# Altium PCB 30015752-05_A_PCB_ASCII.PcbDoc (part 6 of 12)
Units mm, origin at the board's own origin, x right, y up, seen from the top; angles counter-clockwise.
Board outline 100.05 x 72 mm, 10 copper layers (Top, GND_2, Signal_3, Signal_4, PWR_5, GND_6, Signal_7, Signal_8, GND_9, Bottom), stack 1.493 mm thick; 577 components, 546 nets, 2389 pads, 1412 vias.
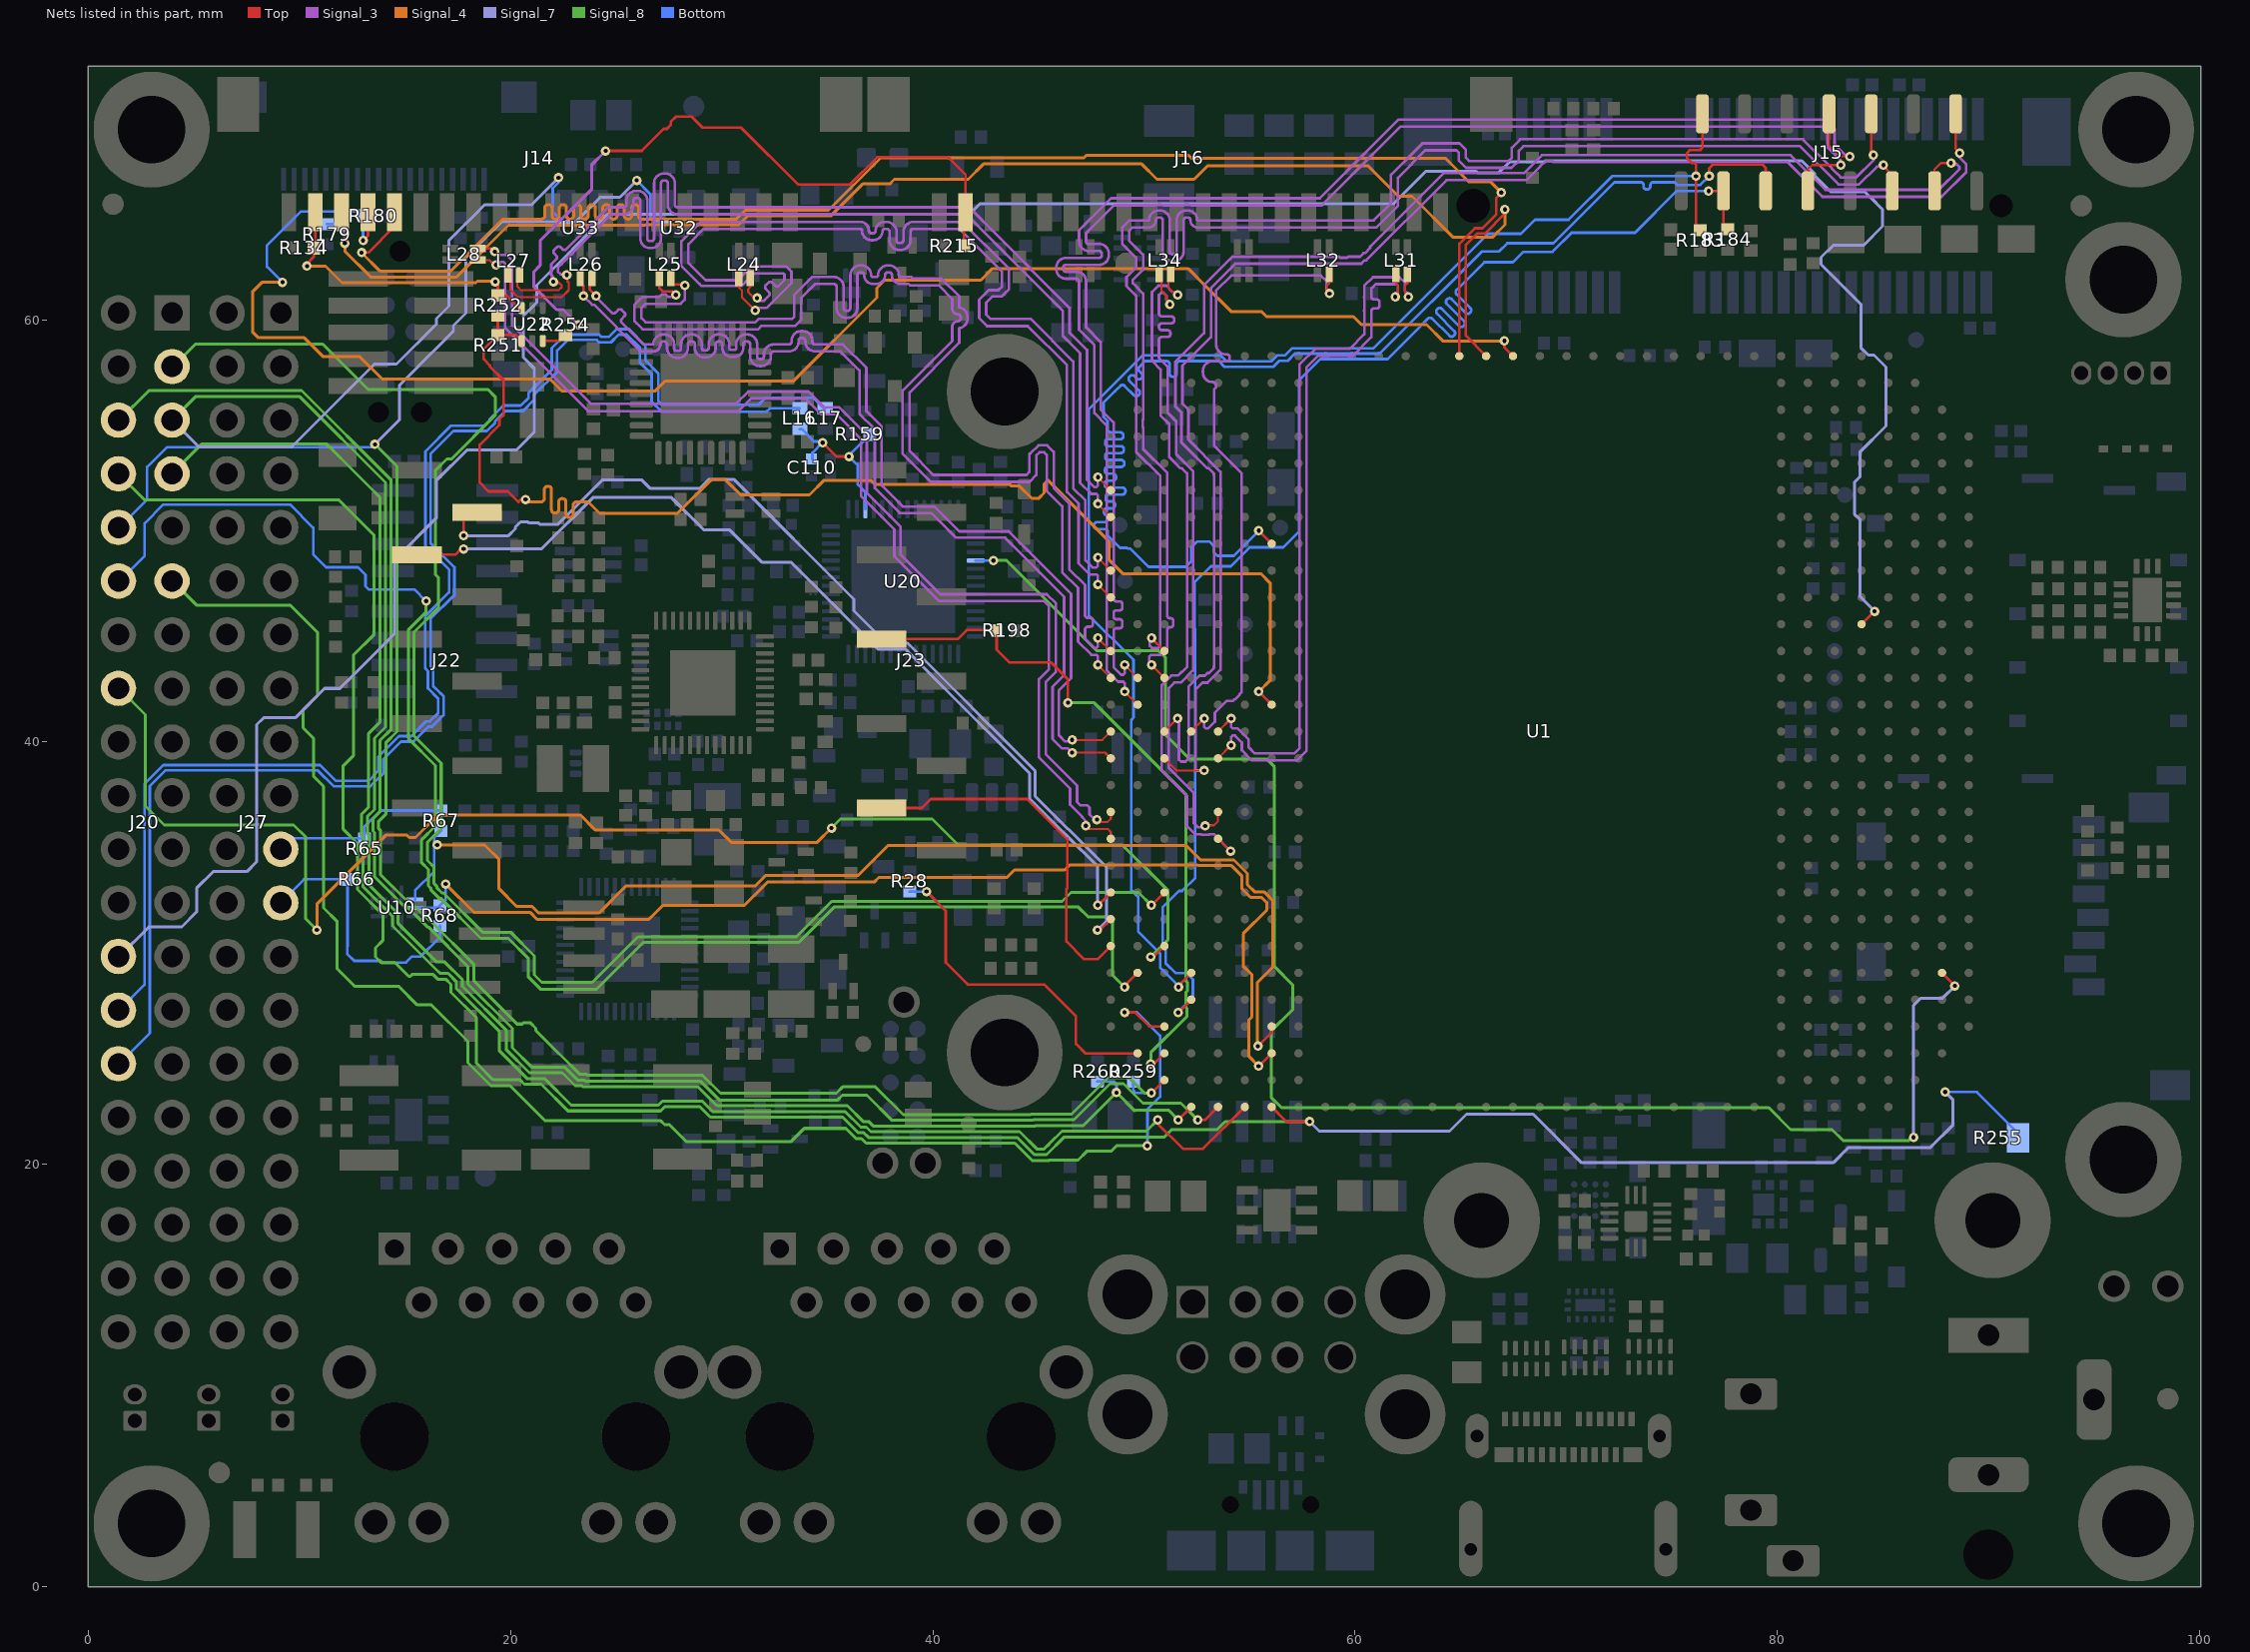
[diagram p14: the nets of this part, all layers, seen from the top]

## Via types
v1: diameter 0.45, hole 0.2, Top to Bottom, tented both sides, 1412 vias

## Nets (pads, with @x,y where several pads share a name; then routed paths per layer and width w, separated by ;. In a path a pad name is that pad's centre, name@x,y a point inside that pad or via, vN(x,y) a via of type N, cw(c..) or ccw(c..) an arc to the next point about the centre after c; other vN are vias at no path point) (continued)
LTE_SYNC: J20.26 U1.E11 | length 136.6
  Top w0.127: U1.E11@83.99,45.58 84.6,46.19 v1(84.61,46.19)
  Signal_7 w0.142: J20.26@1.46,29.84 2.87,31.25 4.423,31.25 5.125,31.952 5.125,33.075 5.915,33.865 7.51,33.865 7.975,34.33 7.975,40.825 8.3,41.15 9.802,41.15 11.192,42.54 11.919,42.54 14.512,45.133 14.512,48.633 16.479,50.6 16.479,52.379 17.925,53.825 20.275,53.825 21.112,54.662 21.112,57.706 20.602,58.215 20.602,60.179 21.238,60.815 21.238,61.643 24.59,64.995 41.732,64.995 42.231,65.494 61.819,65.494 63.346,67.021 65.738,67.021 65.79,66.969 66.81,66.969 67.312,67.471 68.953,67.471 69.005,67.523 81.16,67.523 81.773,66.91 81.773,66.818 82.521,66.071 84.128,66.071 84.412,65.787 84.423,65.787 84.987,65.223 84.987,64.427 84.085,63.525 82.637,63.525 82.075,62.963 82.075,62.621 83.96,60.737 83.96,58.675 84.31,58.325 84.58,58.325 85.148,57.757 85.148,54.973 83.908,53.733 83.908,52.553 83.648,52.294 83.648,50.8 83.923,50.525 83.923,46.877 v1(84.61,46.19)
M40_UART_RX: J27.23 R66.1 R68.1 | length 12.8
  Bottom w0.127: J27.23@9.1,32.38 10.22,33.5 12.22,33.5 12.245,33.475 R66.1@12.245,33.5 12.275,33.47 12.275,30.338 12.259,30.322 12.259,29.978 12.597,29.641 13.849,29.641 13.929,29.561 15.048,29.561 15.329,29.842 15.742,29.842 16.65,30.75 R68.1@16.65,31.295
M40_UART_RX_1V8: R68.2 U1.AG27 U10.9 | length 53.6
  Top w0.127: v1(55.43,24.65) 55.44,24.65 U1.AG27@56.05,25.26
  Signal_4 w0.142: v1(16.925,33.275) 18.26,31.94 20.915,31.94 21.256,31.6 26.55,31.6 27.206,32.256 31.056,32.256 32.167,33.367 37.217,33.367 37.437,33.587 43.512,33.587 43.869,33.944 46.25,33.944 46.488,34.183 52.538,34.183 52.573,34.148 54.151,34.148 54.631,33.668 54.631,33.069 55.057,32.643 55.575,32.643 55.823,32.395 55.823,32.045 54.7,30.922 54.7,29.396 55.106,28.99 55.106,26.979 54.977,26.85 54.977,25.103 v1(55.43,24.65)
  Bottom w0.127: U10.9@15.475,32.15 16.545,32.15 R68.2@16.65,32.255 16.925,32.53 v1(16.925,33.275)
M40_UART_TX: J27.21 R65.1 R67.1 | length 8.7
  Bottom w0.127: J27.21@9.1,34.92 9.63,35.45 13.055,35.45 R65.1@13.075,35.43 13.075,36 13.83,36.755 R67.1@16.7,36.755
M40_UART_TX_1V8: R67.2 U1.AG26 U10.8 | length 56.6
  Top w0.127: v1(55.4,25.6) 56.05,26.25 U1.AG26@56.05,26.53
  Signal_4 w0.142: v1(16.526,35.127) 18.773,35.127 19.45,34.45 19.45,33.05 20.29,32.21 21.027,32.21 21.336,31.9 24.179,31.9 25.463,33.183 31.583,33.183 32.075,33.675 36.45,33.675 37.875,35.1 52.002,35.1 52.685,34.417 54.262,34.417 54.9,33.779 54.9,33.25 55.238,32.912 55.687,32.912 56.092,32.507 56.092,29.328 55.375,28.611 55.375,25.625 v1(55.4,25.6)
  Bottom w0.127: U10.8@15.475,32.55 15.475,32.962 16.385,33.873 16.385,35.48 R67.2@16.7,35.795
MCA_CLKOUT32K: J20.3 U1.AL21 | length 82
  Top w0.127: v1(50.35,32.27) 50.36,32.27 U1.AL21@50.97,32.88
  Signal_8 w0.142: J20.3@4,57.78 5.07,58.85 11.1,58.85 13.246,56.704 18.921,56.704 19.271,56.354 19.271,55.473 17.209,53.41 16.986,53.41 16.43,52.854 16.43,47.947 16.573,47.804 16.573,46.35 15.421,45.198 15.421,40.29 16.712,39 16.712,35.911 16.057,35.256 16.057,34.397 16.378,34.076 16.378,33.297 16.502,33.173 16.502,33.1 16.75,32.852 16.823,32.852 18.7,30.975 20.025,30.975 21.122,29.878 21.122,28.972 21.477,28.617 23.873,28.617 26.031,30.775 33.531,30.775 35.208,32.452 46.127,32.452 46.55,32.875 49.745,32.875 v1(50.35,32.27)
MCA_IO5: J20.10 R259.1 U1.AL28 U32.4 | length 104
  Top w0.127: v1(50.35,23.38) 50.36,23.38 U1.AL28@50.97,23.99
  Signal_8 w0.142: v1(13.575,54.1) 14.613,53.062 14.613,40.489 14.088,39.963 14.088,36.586 13.752,36.25 13.752,35.9 13.827,35.825 13.827,33.735 15.016,32.546 15.141,32.546 16.181,31.506 16.228,31.506 18.251,29.483 18.251,28.701 20.306,26.646 20.548,26.646 20.6,26.698 20.95,26.698 21.198,26.45 21.198,26.341 22.323,25.215 22.331,25.215 23.285,24.262 23.598,24.262 23.645,24.215 29.097,24.215 29.942,23.369 35.428,23.369 35.729,23.67 37.28,23.67 38.598,22.352 38.699,22.352 38.701,22.354 40.601,22.354 40.603,22.352 44.621,22.352 44.651,22.382 46.576,22.382 48.294,24.1 49.3,24.1 50.02,23.38 v1(50.35,23.38)
  Signal_7 w0.142: v1(13.575,54.1) 14.725,55.25 14.725,56.883 17.292,59.45 17.292,59.721 17.883,60.312 17.883,62.958 19.562,64.637 23.088,64.637 24.255,65.803 25.178,65.803 v1(25.975,66.6)
  Bottom w0.127: J20.10@1.46,50.16 2.788,51.488 2.788,53.03 3.728,53.97 13.445,53.97 v1(13.575,54.1) ; v1(25.975,66.6) 26.619,65.955 26.619,64.881 26.9,64.6 U32.4@27.19,64.6 ; R259.1@49.5,23.92 49.5,23.5 49.62,23.38 v1(50.35,23.38)
MCA_IO6: J20.5 R260.1 U1.AK29 U33.4 | length 107.8
  Top w0.127: v1(51.62,22.11) 51.63,22.11 U1.AK29@52.24,22.72
  Signal_8 w0.142: J20.5@3.965,55.245 5.095,56.375 9.994,56.375 14.075,52.294 14.075,40.712 13.549,40.186 13.549,36.809 13.213,36.473 13.213,35.677 13.288,35.602 13.288,33.248 14.675,31.862 14.675,31.404 16.498,29.581 16.881,29.581 17.712,28.75 17.712,28.43 19.81,26.333 19.81,25.413 20.886,24.337 22.448,24.337 23.062,23.723 23.375,23.723 23.422,23.676 28.874,23.676 29.77,22.78 35.951,22.78 36.7,22.031 36.96,22.031 37.176,21.815 38.346,21.815 38.348,21.813 38.922,21.813 38.924,21.815 40.378,21.815 40.38,21.813 44.844,21.813 44.874,21.843 47.143,21.843 v1(48.7,23.4) 49.563,22.537 49.602,22.575 51.155,22.575 v1(51.62,22.11)
  Signal_7 w0.142: J20.5@3.965,55.245 5.235,53.975 9.625,53.975 13.55,57.9 14.6,57.9 16.485,59.785 16.485,60.056 17.075,60.646 17.075,63.75 18.769,65.444 20.994,65.444 v1(22.275,66.725)
  Bottom w0.127: v1(22.275,66.725) 22.275,66.512 21.994,66.232 21.994,65.121 U33.4@22.515,64.6 ; R260.1@47.8,23.92 48.58,23.92 48.7,23.8 v1(48.7,23.4)
MCA_IO7: J20.6 U1.AJ29 | length 82
  Top w0.127: v1(52.55,22.1) 52.89,22.1 U1.AJ29@53.51,22.72
  Signal_8 w0.142: J20.6@1.46,55.24 2.87,56.65 10.1,56.65 14.344,52.406 14.344,40.6 13.818,40.075 13.818,36.698 13.483,36.362 13.483,35.788 13.558,35.713 13.558,33.623 14.904,32.277 15.023,32.277 15.95,31.35 ; 15.951,31.35 16.064,31.236 16.117,31.236 17.982,29.371 17.982,28.541 20.079,26.444 20.079,25.525 20.998,24.606 22.56,24.606 23.173,23.992 23.487,23.992 23.534,23.945 28.985,23.945 29.882,23.049 35.489,23.049 35.715,23.275 36.875,23.275 38.066,22.084 38.458,22.084 38.459,22.083 38.811,22.083 38.812,22.084 40.49,22.084 40.491,22.083 44.733,22.083 44.763,22.113 46.688,22.113 48.398,23.823 49.031,23.823 49.954,22.9 51.75,22.9 v1(52.55,22.1)
MCA_IO8: J20.7 U1.AH29 | length 80.4
  Top w0.127: v1(50.65,22.1) 50.65,21.937 51.853,20.735 52.794,20.735 U1.AH29@54.78,22.72
  Signal_8 w0.142: J20.7@3.965,52.705 5.385,54.125 11.273,54.125 12.723,52.675 13.271,52.127 13.806,51.593 13.806,40.932 13.28,40.407 13.28,36.921 12.944,36.585 12.944,35.565 13.019,35.49 13.019,33.137 14.406,31.75 14.406,31.292 16.435,29.263 16.443,29.263 16.662,29.044 17.038,29.044 17.443,28.638 17.443,28.318 19.475,26.286 19.475,25.367 20.775,24.067 21.608,24.067 22.875,22.8 26.996,22.8 27.19,22.993 29.082,22.993 29.575,22.5 35.85,22.5 36.588,21.762 36.848,21.762 37.064,21.546 38.234,21.546 38.236,21.544 39.034,21.544 39.036,21.546 40.266,21.546 40.268,21.544 44.107,21.544 44.925,20.727 45.275,20.727 45.523,20.975 45.523,20.979 46.118,21.574 50.124,21.574 v1(50.65,22.1)
MCA_IO9: J20.8 R255.2 U1.AG29 | length 126.3
  Top w0.127: U1.AG29@56.05,22.72 56.745,22.025 v1(57.85,22.025)
  Signal_8 w0.142: J20.8@1.425,52.705 2.655,51.475 11.85,51.475 13.537,49.788 13.537,45.1 12.55,44.113 12.55,39.35 12.075,38.875 12.075,35.875 12.75,35.2 12.75,33.025 13.95,31.825 13.95,30.6 13.6,30.25 13.6,29.825 13.875,29.55 14.525,29.55 15.175,28.9 15.245,28.9 15.339,28.994 16.331,28.994 16.55,28.775 16.926,28.775 17.174,28.527 17.174,28.151 18.375,26.95 18.375,24.8 19.175,24 20.444,24 20.646,23.798 21.45,23.798 22.718,22.531 27.108,22.531 27.301,22.724 28.97,22.724 29.463,22.231 29.994,22.231 30,22.225 35.744,22.225 36.477,21.492 36.737,21.492 36.954,21.275 37.113,21.275 37.115,21.277 38.123,21.277 38.125,21.275 39.145,21.275 39.147,21.277 40.155,21.277 40.157,21.275 43.996,21.275 44.813,20.458 45.387,20.458 46.228,21.299 50.974,21.299 51.325,21.65 53.475,21.65 53.85,22.025 v1(57.85,22.025)
  Signal_7 w0.142: v1(57.85,22.025) 58.3,21.575 64.475,21.575 65.277,22.377 68.433,22.377 70.733,20.077 82.652,20.077 83.375,20.8 87.25,20.8 88.325,21.875 88.325,23.05 v1(87.95,23.425)
  Bottom w0.127: v1(87.95,23.425) 89.45,23.425 91.4,21.475 R255.2@91.4,21.25
MCA_IO14: J20.11 U1.AL26 | length 78
  Top w0.127: v1(49.08,27.2) 49.582,27.2 50.252,26.53 U1.AL26@50.97,26.53
  Signal_8 w0.142: J20.11@4,47.62 5.147,46.473 9.577,46.473 10.85,45.2 10.85,42.2 10.175,41.525 10.175,40.675 10.673,40.177 10.673,38.372 11.141,37.903 11.141,32.144 11.787,31.498 11.787,29.264 12.61,28.44 13.955,28.44 13.963,28.433 14.537,28.433 14.545,28.44 14.69,28.44 15.581,27.55 16.256,27.55 17.978,25.828 17.978,24.809 19.061,23.725 19.975,23.725 21.638,22.061 27.118,22.061 27.301,21.878 27.522,21.878 28.315,21.085 33.29,21.085 33.909,21.703 35.885,21.703 36.365,21.223 36.625,21.223 36.843,21.006 37.225,21.006 37.227,21.007 38.011,21.007 38.013,21.006 39.257,21.006 39.259,21.007 40.043,21.007 40.045,21.006 43.884,21.006 44.702,20.188 45.498,20.188 45.512,20.202 46.875,20.202 47.291,20.618 48.445,20.618 48.703,20.876 v1(50.152,20.876)
  Bottom w0.127: v1(49.08,27.2) 49.658,27.2 50.766,26.092 50.766,23.208 50.166,22.608 50.166,20.889 v1(50.152,20.876)
MCA_IO17: J20.16 U1.AL23 | length 69
  Top w0.127: v1(50.325,29.825) 50.455,29.825 U1.AL23@50.97,30.34
  Signal_8 w0.142: J20.16@1.46,42.54 2.7,41.3 2.7,36.975 3.6,36.075 9.725,36.075 10.3,35.5 10.3,31.625 v1(10.825,31.1) ; v1(35.2,35.925) 35.625,36.35 39.975,36.35 41.2,35.125 48.975,35.125 51.144,32.956 51.144,31.192 51.129,31.177 51.129,30.826 51.144,30.811 51.144,30.644 v1(50.325,29.825)
  Signal_4 w0.142: v1(10.825,31.1) 10.825,32.325 14.092,35.592 15.087,35.592 15.204,35.475 15.488,35.475 16.563,36.55 23.3,36.55 24.025,35.825 29.875,35.825 30.448,35.252 34.527,35.252 v1(35.2,35.925)
MCA_UART2_CTS: J23.9 U1.AN23 | length 17.3
  Top w0.127: J23.9@37.567,36.875 39.475,36.875 39.9,37.3 44.475,37.3 46.368,35.407 46.368,33.08 46.325,33.037 46.325,30.55 47.15,29.725 47.815,29.725 U1.AN23@48.43,30.34
MCA_UART2_RTS: J23.5 R198.2 U1.AL27 | length 33.4
  Top w0.127: J23.5@37.567,44.875 41.175,44.875 41.6,45.3 43.02,45.3 R198.2@43.02,45.275 43.02,44.38 43.625,43.775 45.591,43.775 46.4,42.966 v1(46.4,41.86) ; v1(50.325,24.75) 50.46,24.75 U1.AL27@50.97,25.26
  Signal_8 w0.142: v1(46.4,41.86) 47.643,41.86 51.998,37.505 51.998,28.68 52.057,28.621 52.057,28.217 51.998,28.158 51.998,27.41 52.043,27.365 52.043,27.015 50.325,25.297 v1(50.325,24.75)
MCA_UART2_RX: J22.2 U1.AN22 | length 46.6
  Top w0.127: v1(17.775,49.775) 17.775,50.725 17.625,50.875 J22.2@18.417,50.875 ; v1(47.8,31.1) 47.92,31.1 U1.AN22@48.43,31.61
  Signal_7 w0.142: v1(17.775,49.775) 19.9,49.775 20.227,50.102 20.227,50.175 20.475,50.423 20.825,50.423 20.877,50.371 21.329,50.371 21.402,50.298 22.237,50.298 24.364,52.426 26.199,52.426 26.623,52.002 28.962,52.002 29.388,52.428 30.592,52.428 36.26,46.76 36.26,46.217 37.8,44.677 38.809,44.677 44.85,38.637 44.85,37.432 46.4,35.883 46.412,35.883 48.233,34.061 48.233,31.533 v1(47.8,31.1)
MCA_UART2_TX: J22.3 U1.AN21 | length 44
  Top w0.127: J22.3@15.567,48.875 17.375,48.875 17.65,49.15 v1(17.775,49.15) ; v1(47.81,32.27) 47.82,32.27 U1.AN21@48.43,32.88
  Signal_7 w0.142: v1(17.775,49.15) 21.469,49.15 23.899,51.58 25.5,51.58 ; 25.501,51.579 25.852,51.579 27.62,51.58 29.162,50.038 30.381,50.038 31.9,48.519 33.281,48.519 37.392,44.408 38.698,44.408 40.613,42.492 40.613,42.485 44.581,38.518 44.581,37.321 46.288,35.613 46.301,35.613 47.81,34.104 v1(47.81,32.27)
MCA_VIN_DET: R28.2 U1.AM27 | length 16.2
  Top w0.127: v1(39.7,32.92) 40.616,32.004 40.616,29.559 41.654,28.521 45.264,28.521 46.779,27.005 46.779,25.708 47.237,25.25 49.69,25.25 U1.AM27@49.7,25.26
  Bottom w0.127: R28.2@38.9,32.92 v1(39.7,32.92)
MCA_VREF_OUT: J20.12 U1.AM24 | length 75.8
  Top w0.127: v1(49.08,28.4) 49.08,28.45 U1.AM24@49.7,29.07
  Signal_8 w0.142: v1(16,46.675) 16,46.157 15.152,45.309 15.152,40.179 16.442,38.888 16.442,36.022 15.788,35.368 15.788,34.286 16.108,33.965 16.108,33.186 16.233,33.062 16.233,32.988 16.638,32.583 16.712,32.583 18.589,30.706 19.894,30.706 20.85,29.75 20.85,28.863 21.413,28.3 24.075,28.3 26.281,30.506 33.642,30.506 35.32,32.183 46.892,32.183 47.35,31.725 48.275,31.725 48.5,31.5 48.5,28.98 v1(49.08,28.4)
  Bottom w0.127: J20.12@1.46,47.62 2.664,48.824 2.664,50.366 3.548,51.25 9.552,51.25 10.649,50.153 10.649,48.891 11.265,48.275 12.775,48.275 13.125,47.925 13.125,47.375 13.275,47.225 15.45,47.225 v1(16,46.675)
MCLK_OUT0: U1.B24 U20.5 | length 77.6
  Top w0.127: U1.B24@87.8,29.07 88.41,28.46 v1(88.41,28.45)
  Signal_8 w0.142: v1(42.875,48.6) 43.5,48.6 47.78,44.32 50.7,44.32 51.025,43.995 51.025,40.325 52.15,39.2 55.805,39.2 56.18,38.825 56.18,29.36 57.04,28.5 57.04,27.325 56.025,26.31 56.025,23.175 56.52,22.68 79.6,22.68 80.632,21.648 82.598,21.648 83.113,21.133 86.224,21.133 86.367,21.275 v1(86.45,21.275)
  Signal_7 w0.142: v1(86.45,21.275) 86.45,27.525 86.8,27.875 87.835,27.875 v1(88.41,28.45)
  Bottom w0.127: U20.5@42.03,48.6 v1(42.875,48.6)
MIC_BIAS: C110.2 L16.2 R159.1 U20.45 | length 8.1
  Top w0.127: v1(34.78,54.18) 35.435,53.525 v1(36.025,53.525)
  Bottom w0.127: L16.2@33.7,54.82 33.79,54.82 34.373,54.237 34.688,54.237 34.745,54.18 v1(34.78,54.18) 34.3,53.7 C110.2@34.3,53.4 ; U20.45@36.8,51.03 36.8,51.836 36.441,52.195 36.441,53.11 v1(36.025,53.525) 36.025,53.57 37.005,54.55 R159.1@37.005,54.575
MIC_N: J20.28 L17.1 | length 66.3
  Bottom w0.127: J20.28@1.46,27.3 2.655,28.495 2.655,38.017 3.548,38.909 10.975,38.909 11.725,38.159 13.259,38.159 13.725,38.625 13.725,39.29 14.712,40.278 15.3,40.278 16.003,40.98 16.177,40.98 16.57,41.373 16.57,42.059 16.083,42.545 16.083,43.36 15.954,43.489 15.954,45.954 17.084,47.084 17.084,48.176 15.966,49.294 15.966,53.765 17.185,54.985 18.772,54.985 19.016,55.228 19.016,55.303 19.647,55.935 20.485,55.935 20.85,56.3 20.85,56.53 21.95,57.63 21.95,58.65 22.6,59.3 24.187,59.3 24.303,59.184 24.647,59.184 25.017,59.554 25.605,59.554 26.379,58.78 26.379,58.081 27,57.46 27,56.155 27.18,55.975 31.75,55.975 32.075,56.3 34.34,56.3 34.835,55.805 L17.1@34.9,55.805
MIC_P: J20.30 L16.1 | length 67.1
  Bottom w0.127: J20.30@1.46,24.76 2.909,26.209 2.909,37.912 3.653,38.655 10.87,38.655 11.62,37.905 13.365,37.905 13.979,38.52 13.979,39.185 14.817,40.024 15.405,40.024 16.108,40.726 16.283,40.726 16.824,41.267 16.824,42.173 16.687,42.309 16.678,42.309 16.434,42.553 16.434,42.559 16.385,42.608 16.379,42.608 16.337,42.65 16.337,43.466 16.208,43.595 16.208,45.833 17.338,46.963 17.338,48.281 16.22,49.399 16.22,53.66 17.29,54.731 18.877,54.731 19.27,55.123 19.27,55.198 19.752,55.681 20.59,55.681 21.104,56.195 21.104,56.425 22.204,57.525 22.204,58.545 22.705,59.046 24.082,59.046 24.198,58.93 24.752,58.93 25.122,59.3 25.5,59.3 26.125,58.675 26.125,57.975 26.68,57.42 26.68,56.115 27.145,55.65 32.125,55.65 32.28,55.805 L16.1@33.7,55.805
MIPI0_IRQ_N_5V: J14.19 R134.1 R252.2 U22.6 | length 14.1
  Top w0.127: v1(10.36,62.54) 10.36,62.66 10.68,62.98 R134.1@10.68,63.4 10.75,63.47 J14.19@10.75,65.1 ; v1(19.275,61.8) 19.4,61.675 R252.2@19.4,61.155 19.795,61.155 20.395,60.555 U22.6@20.525,60.555
  Signal_4 w0.142: v1(10.36,62.54) 11.235,62.54 12.021,61.754 18.356,61.754 18.425,61.823 19.252,61.823 v1(19.275,61.8)
MIPI1_IRQ_N_5V: J16.19 R215.1 R254.2 U22.3 | length 36.1
  Top w0.127: U22.3@21.525,58.995 22.325,58.995 R254.2@22.6,59.27 23.08,59.75 v1(23.225,59.75) ; v1(24.5,68) 26.212,68 27.253,69.041 27.403,69.041 27.584,69.222 27.584,69.372 27.828,69.615 28.584,69.615 29.1,69.1 30.925,69.1 33.617,66.407 36.083,66.407 37.375,67.7 40.725,67.7 41.55,66.875 J16.19@41.55,65.1 41.48,65.03 R215.1@41.48,63.5
  Signal_3 w0.142: v1(23.225,59.75) 22.494,60.481 22.179,60.481 21.106,61.554 21.106,62.282 21.398,62.575 21.398,63.742 23.848,66.192 23.848,67.348 v1(24.5,68)
MIPI_CSI0_CLK_N: J15.8 U1.AM14 | length 69.8
  Top w0.102: v1(49.09,42.39) 49.09,42.38 U1.AM14@49.7,41.77 ; J15.8@82.45,69.75 82.45,68.25 82.966,67.734 v1(83.432,67.734)
  Signal_3 w0.124: v1(49.09,42.39) 49.09,42.787 49.017,42.86 48.777,42.86 48.234,43.403 48.234,54.999 47.65,55.583 47.65,58.803 46.928,59.525 46.928,61.819 ccw(c46.798,61.819) 46.798,61.948 46.307,61.948 cw(c46.307,62.408) 45.847,62.408 45.847,62.473 cw(c46.307,62.473) 46.307,62.933 47.879,62.933 ccw(c47.879,63.063) 48.008,63.063 48.008,63.128 ccw(c47.879,63.128) 47.879,63.258 47.387,63.258 cw(c47.387,63.717) 46.928,63.717 46.928,64.236 48.447,65.755 58.33,65.755 62.055,69.48 82.262,69.48 82.709,69.033 82.709,68.312 83.287,67.734 v1(83.432,67.734)
MIPI_CSI0_CLK_P: J15.7 U1.AM13 | length 69.7
  Top w0.102: v1(49.09,43.66) 49.09,43.65 U1.AM13@49.7,43.04 ; J15.7@81.45,66.1 81.45,67.125 81.675,67.35 81.697,67.328 v1(83.004,67.328)
  Signal_3 w0.124: v1(49.09,43.66) 49.09,43.263 49.017,43.19 48.914,43.19 48.564,43.54 48.564,45.125 48.564,45.262 cw(c48.692,45.262) 48.692,45.389 48.847,45.389 ccw(c48.847,45.517) 48.974,45.517 48.974,45.687 ccw(c48.847,45.687) 48.847,45.814 48.692,45.814 cw(c48.692,45.941) 48.564,45.941 48.564,46.111 cw(c48.692,46.111) 48.692,46.238 48.847,46.238 ccw(c48.847,46.366) 48.974,46.366 48.974,46.535 ccw(c48.847,46.535) 48.847,46.663 48.692,46.663 cw(c48.692,46.79) 48.564,46.79 48.564,46.875 48.564,55.136 47.95,55.75 47.95,58.95 47.258,59.642 47.258,61.819 ccw(c46.798,61.819) 46.798,62.278 46.307,62.278 cw(c46.307,62.408) 46.177,62.408 46.177,62.473 cw(c46.307,62.473) 46.307,62.603 47.879,62.603 ccw(c47.879,63.063) 48.338,63.063 48.338,63.128 ccw(c47.879,63.128) 47.879,63.588 47.387,63.588 cw(c47.387,63.717) 47.258,63.717 47.258,64.099 48.584,65.425 50.518,65.425 50.525,65.432 50.566,65.432 50.57,65.436 50.625,65.436 50.633,65.443 50.647,65.443 50.65,65.446 50.81,65.446 50.812,65.443 50.827,65.443 50.834,65.436 50.889,65.436 50.893,65.432 50.935,65.432 50.941,65.425 51.827,65.425 51.834,65.432 51.876,65.432 51.88,65.436 51.935,65.436 51.942,65.443 51.956,65.443 51.959,65.446 52.119,65.446 52.122,65.443 52.136,65.443 52.143,65.436 52.198,65.436 52.202,65.432 52.244,65.432 52.251,65.425 58.425,65.425 62.15,69.15 82.125,69.15 82.379,68.896 82.379,68.175 83.004,67.55 v1(83.004,67.328)
MIPI_CSI0_DATA0_N: J15.14 U1.AL16 | length 69.5
  Top w0.102: U1.AL16@50.97,39.23 51.55,38.65 v1(52.85,38.65) ; J15.14@88.45,69.75 88.45,68.09 v1(88.64,67.9)
  Signal_3 w0.124: v1(52.85,38.65) 52.525,38.65 52.446,38.729 52.446,42.486 52.771,42.811 53.016,42.811 53.63,43.426 53.63,52.799 52.108,54.321 52.108,55.74 51.82,56.028 51.82,57.82 53.176,59.176 53.176,61.499 54.335,62.658 60.297,62.658 60.453,62.814 60.527,62.814 64.326,66.613 68.129,66.613 68.766,67.25 68.766,67.272 69.008,67.514 69.352,67.514 69.404,67.462 80.5,67.462 82.138,65.824 87.78,65.824 88.952,66.996 88.952,67.373 v1@88.612,67.713
MIPI_CSI0_DATA0_P: J15.13 U1.AL15 | length 69.9
  Top w0.102: U1.AL15@50.97,40.5 51.58,41.11 v1(51.59,41.11) ; J15.13@87.45,66.1 87.45,67.125 87.75,67.425 v1(88.225,67.425)
  Signal_3 w0.124: v1(51.59,41.11) 51.66,41.04 51.66,39.165 51.75,39.075 51.975,39.075 52.116,39.216 52.116,42.623 52.635,43.142 52.879,43.142 52.998,43.261 53.072,43.261 53.314,43.503 53.314,43.577 53.325,43.588 53.325,52.637 53.314,52.648 53.314,52.722 53.072,52.964 52.998,52.964 51.778,54.185 51.778,55.603 51.49,55.891 51.49,58.015 52.846,59.371 52.846,61.635 54.198,62.988 59.232,62.988 59.281,62.939 59.624,62.939 59.673,62.988 60.234,62.988 60.41,63.164 60.475,63.164 60.717,63.407 60.717,63.471 64.189,66.943 67.992,66.943 68.841,67.792 80.637,67.792 82.275,66.154 87.643,66.154 88.622,67.133 88.622,67.236 88.495,67.363 88.287,67.363 v1(88.225,67.425)
MIPI_CSI0_DATA1_N: J15.11 U1.AL13 | length 69.7
  Top w0.102: v1(50.36,43.66) 50.36,43.65 U1.AL13@50.97,43.04 ; v1(85.029,67.328) 85.029,67.271 85.45,66.85 J15.11@85.45,66.1
  Signal_3 w0.124: v1(50.36,43.66) 50.25,43.77 50.25,44.05 50.33,44.13 50.822,44.13 51.104,44.412 51.104,45.325 cw(c51.218,45.325) 51.218,45.438 51.261,45.438 ccw(c51.261,45.566) 51.388,45.566 51.388,45.735 ccw(c51.261,45.735) 51.261,45.863 51.232,45.863 cw(c51.232,45.99) 51.104,45.99 51.104,46.075 51.104,52.738 49.958,53.884 49.958,54.906 49.946,54.918 49.946,55.262 49.958,55.274 49.958,61.242 49.475,61.725 49.475,61.892 49.958,62.375 49.958,63.092 49.3,63.75 49.3,64.225 49.45,64.375 50.229,64.375 ccw(c50.229,64.714) 50.567,64.714 cw(c50.697,64.714) 50.697,64.843 50.762,64.843 cw(c50.762,64.714) 50.892,64.714 50.892,63.235 ccw(c51.352,63.235) 51.352,62.775 51.417,62.775 ccw(c51.417,63.235) 51.877,63.235 51.877,64.714 cw(c52.006,64.714) 52.006,64.843 52.072,64.843 cw(c52.072,64.714) 52.201,64.714 ccw(c52.54,64.714) 52.54,64.375 61.017,64.375 62.03,65.388 62.03,66.727 63.328,68.025 64.806,68.025 64.906,67.924 64.906,67.552 65.263,67.195 67.412,67.195 67.755,67.538 67.755,68.011 67.969,68.225 81.072,68.225 82.892,66.406 83.864,66.406 84.713,67.254 84.954,67.254 v1(85.029,67.328)
MIPI_CSI0_DATA1_P: J15.10 U1.AL12 | length 69.6
  Top w0.102: v1(50.36,44.93) 50.36,44.92 U1.AL12@50.97,44.31 ; J15.10@84.45,69.75 84.45,67.858 84.505,67.803 v1(84.554,67.803)
  Signal_3 w0.124: 50.229,64.705 49.313,64.705 48.97,64.362 48.97,63.605 49.628,62.947 49.628,62.478 49.175,62.025 49.175,61.591 49.628,61.138 49.628,53.747 50.774,52.601 50.774,46.1 50.768,46.093 50.768,45.99 50.765,45.99 50.765,45.952 50.771,45.946 50.771,45.909 50.774,45.905 50.774,45.868 50.774,45.443 50.773,45.442 50.773,45.407 50.77,45.404 50.77,45.367 50.766,45.362 50.766,45.325 50.768,45.325 50.768,45.222 50.774,45.215 50.774,44.549 50.685,44.46 50.38,44.46 50.28,44.56 50.28,44.85 v1(50.36,44.93) ; 50.237,64.714 cw(c50.697,64.714) 50.697,65.174 50.762,65.174 cw(c50.762,64.714) 51.222,64.714 51.222,63.235 ccw(c51.352,63.235) 51.352,63.105 51.417,63.105 ccw(c51.417,63.235) 51.547,63.235 51.547,64.714 cw(c52.006,64.714) 52.006,65.174 52.072,65.174 cw(c52.072,64.714) 52.531,64.714 ; 52.54,64.705 60.88,64.705 61.7,65.525 61.7,66.864 63.191,68.355 64.942,68.355 65.236,68.061 65.236,67.689 65.4,67.525 67.275,67.525 67.425,67.675 67.425,68.148 67.833,68.555 81.209,68.555 82.59,67.174 82.59,67.157 82.832,66.914 82.85,66.914 83.028,66.736 83.727,66.736 84.554,67.563 v1(84.554,67.803)
MIPI_CSI0_I2C0_SCL: J15.3 R184.1 U1.AK25 | length 69.4
  Top w0.127: v1(51.62,27.19) 51.63,27.19 U1.AK25@52.24,27.8 ; v1(76.75,66.1) 77.425,66.1 J15.3@77.45,66.075 ; J15.3@77.45,66.1 J15.3@77.45,66.075 ; R184.1@77.5,64.23 77.45,64.28 J15.3@77.45,66.075
  Bottom w0.127: v1(51.62,27.19) 52.32,27.89 52.32,28.76 52.019,29.061 51.499,29.061 51.029,29.531 51.029,30.252 50.883,30.398 50.883,32.171 51.658,32.946 51.805,32.946 52.429,33.57 52.429,45.33 52.4,45.36 52.4,47.557 53.167,48.325 54.114,48.325 55.01,49.221 56.596,49.221 57.34,49.965 57.34,57.126 58.357,58.142 61.537,58.142 63.222,59.828 63.319,59.925 63.447,60.052 cw(c63.551,59.948) 63.655,60.052 64.467,59.24 ccw(c64.571,59.344) 64.675,59.24 64.698,59.263 ccw(c64.594,59.367) 64.698,59.471 63.886,60.283 cw(c63.99,60.387) 63.886,60.491 63.909,60.514 cw(c64.013,60.41) 64.117,60.514 64.929,59.702 ccw(c65.033,59.806) 65.137,59.702 65.16,59.725 ccw(c65.056,59.829) 65.16,59.933 64.348,60.746 cw(c64.452,60.85) 64.348,60.954 64.371,60.977 cw(c64.475,60.873) 64.58,60.977 65.229,60.327 ccw(c65.333,60.431) 65.437,60.327 65.461,60.35 ccw(c65.357,60.454) 65.461,60.558 64.811,61.208 cw(c64.915,61.312) 64.811,61.416 64.822,61.428 66.121,62.726 67.476,62.726 67.967,63.217 69.351,63.217 70.259,64.125 73.263,64.125 75.238,66.1 v1(76.75,66.1)
MIPI_CSI0_I2C0_SDA: J15.2 R183.1 U1.AK24 | length 70.2
  Top w0.127: v1(51.634,28.393) 51.634,28.456 51.63,28.46 U1.AK24@52.24,29.07 ; R183.1@76.35,64.23 76.3,64.28 76.34,64.32 76.15,64.51 v1(76.15,66.8) 76.15,67.35 76.075,67.425 75.95,67.425 75.725,67.65 75.725,67.9 75.863,68.037 76.338,68.037 76.45,68.15 J15.2@76.45,69.75
  Bottom w0.127: v1(51.634,28.393) 51.634,28.446 50.775,29.305 50.775,29.975 49.725,31.025 49.725,32.675 49.4,33 49.4,41.05 49.505,41.156 49.505,43.894 47.385,46.015 47.385,55.747 49.958,58.32 53.63,58.32 53.925,58.025 56.025,58.025 56.309,58.309 56.675,58.309 57.016,58.65 60.875,58.65 66.3,64.075 67.863,64.075 68.528,64.741 70.116,64.741 72.175,66.8 v1(76.15,66.8)
MIPI_CSI0_RESET_N: J15.5 U1.AG8 | length 67.3
  Top w0.127: v1(55.44,50.01) 55.44,50 U1.AG8@56.05,49.39 ; v1(76.775,66.8) 76.775,67.175 76.95,67.35 79.3,67.35 79.45,67.2 J15.5@79.45,66.1
  Bottom w0.127: v1(55.44,50.01) 54.25,48.82 53.48,48.82 53.321,48.98 53.321,49.275 53.095,49.5 52.525,49.5 52.252,49.227 52.252,48.572 51.98,48.3 50.212,48.3 49.357,49.155 49.245,49.155 49.2,49.2 48.875,49.2 48.278,49.797 48.278,49.925 48.278,49.942 ccw(c48.131,49.942) 48.131,50.089 47.786,50.089 cw(c47.786,50.237) 47.638,50.237 47.638,50.269 cw(c47.786,50.269) 47.786,50.416 48.131,50.416 ccw(c48.131,50.564) 48.278,50.564 48.278,50.72 ccw(c48.255,50.72) 48.255,50.743 cw(c48.255,50.891) 48.108,50.891 48.108,50.923 cw(c48.255,50.923) 48.255,51.07 48.278,51.07 48.482,51.07 ccw(c48.482,51.218) 48.629,51.218 48.629,51.25 ccw(c48.482,51.25) 48.482,51.397 48.278,51.397 cw(c48.278,51.484) 48.192,51.484 48.192,51.638 cw(c48.278,51.638) 48.278,51.724 48.976,51.724 ccw(c48.976,51.872) 49.123,51.872 49.123,51.904 ccw(c48.976,51.904) 48.976,52.051 48.278,52.051 cw(c48.278,52.189) 48.141,52.189 48.141,52.241 cw(c48.278,52.241) 48.278,52.378 48.527,52.378 ccw(c48.527,52.526) 48.675,52.526 48.675,52.558 ccw(c48.527,52.558) 48.527,52.705 48.278,52.705 cw(c48.278,52.824) 48.16,52.824 48.16,52.914 cw(c48.278,52.914) 48.278,53.032 48.925,53.032 ccw(c48.925,53.18) 49.072,53.18 49.072,53.212 ccw(c48.925,53.212) 48.925,53.359 48.278,53.359 cw(c48.278,53.458) 48.18,53.458 48.18,53.588 cw(c48.278,53.588) 48.278,53.686 48.9,53.686 ccw(c48.9,53.834) 49.047,53.834 49.047,53.866 ccw(c48.9,53.866) 48.9,54.013 48.278,54.013 cw(c48.278,54.125) 48.167,54.125 48.167,54.229 cw(c48.278,54.229) 48.278,54.34 48.874,54.34 ccw(c48.874,54.488) 49.021,54.488 49.021,54.52 ccw(c48.874,54.52) 48.874,54.667 48.426,54.667 cw(c48.426,54.815) 48.278,54.815 48.278,54.831 48.278,55.197 48.084,55.391 48.084,56.072 48.637,56.625 48.753,56.741 48.88,56.868 cw(c48.984,56.764) 49.088,56.868 49.532,56.424 ccw(c49.636,56.528) 49.74,56.424 49.763,56.447 ccw(c49.659,56.551) 49.763,56.655 49.32,57.099 cw(c49.424,57.203) 49.32,57.307 49.343,57.33 cw(c49.447,57.226) 49.551,57.33 49.66,57.221 ccw(c49.764,57.325) 49.868,57.221 49.891,57.244 ccw(c49.787,57.348) 49.891,57.452 49.782,57.561 cw(c49.886,57.666) 49.782,57.77 49.894,57.881 50.058,58.046 50.725,58.046 50.888,58.046 51.068,58.046 cw(c51.068,57.899) 51.215,57.899 51.215,57.448 ccw(c51.363,57.448) 51.363,57.3 51.395,57.3 ccw(c51.395,57.448) 51.542,57.448 51.542,57.899 cw(c51.69,57.899) 51.69,58.046 51.7,58.046 53.545,58.046 53.82,57.771 56.13,57.771 56.415,58.055 56.805,58.055 57.146,58.396 61.171,58.396 66.009,63.234 66.822,63.234 67.213,63.625 69.4,63.625 72.291,66.516 73.525,66.516 cw(c73.525,66.381) 73.659,66.381 73.659,66.322 ccw(c73.807,66.322) 73.807,66.175 73.839,66.175 ccw(c73.839,66.322) 73.986,66.322 73.986,66.368 cw(c74.134,66.368) 74.134,66.516 74.15,66.516 75.131,66.516 75.262,66.385 76.359,66.385 v1(76.775,66.8)
MIPI_DSI0_CLK_N: L27.1 U1.AN6 | length 49.8
  Top w0.102: L27.1@20.425,62.125 20.315,62.015 20.315,61.572 20.49,61.397 22.276,61.397 22.422,61.543 22.422,61.627 22.302,61.747 22.078,61.747 v1(22.025,61.8) ; v1(47.82,52.55) 47.82,52.54 U1.AN6@48.43,51.93
  Signal_3 w0.124: v1(22.025,61.8) 21.974,61.851 21.974,62.083 21.928,62.129 21.928,62.63 22.099,62.801 22.159,62.861 ccw(c22.069,62.951) 22.159,63.041 22.068,63.132 cw(c22.158,63.222) 22.068,63.312 22.188,63.432 cw(c22.278,63.342) 22.368,63.432 22.459,63.342 ccw(c22.549,63.432) 22.639,63.342 22.747,63.45 24.623,65.326 25.358,65.326 ccw(c25.358,65.455) 25.487,65.455 25.487,65.646 cw(c25.947,65.646) 25.947,66.106 26.012,66.106 cw(c26.012,65.646) 26.472,65.646 26.472,63.855 ccw(c26.602,63.855) 26.602,63.726 26.667,63.726 ccw(c26.667,63.855) 26.797,63.855 26.797,66.466 cw(c27.256,66.466) 27.256,66.926 27.322,66.926 cw(c27.322,66.466) 27.781,66.466 27.781,65.455 ccw(c27.911,65.455) 27.911,65.326 41.716,65.326 42.712,64.33 46.48,60.562 46.48,59.4 47.305,58.575 47.305,52.419 47.644,52.08 47.747,52.08 47.82,52.153 v1(47.82,52.55)
MIPI_DSI0_CLK_P: L27.4 U1.AN7 | length 49.9
  Top w0.102: L27.4@19.875,62.125 19.985,62.015 19.985,61.435 20.353,61.067 22.413,61.067 22.752,61.406 22.752,61.764 22.698,61.818 22.698,62.052 22.66,62.09 v1(22.66,62.12) ; v1(47.82,51.28) 47.82,51.27 U1.AN7@48.43,50.66
  Signal_3 w0.124: v1(22.66,62.12) 22.63,62.12 22.596,62.154 22.37,62.154 22.244,62.28 22.244,62.48 22.315,62.55 22.324,62.55 22.397,62.623 22.398,62.622 22.426,62.649 22.426,62.656 22.452,62.683 22.452,62.688 22.478,62.714 22.786,63.022 22.812,63.048 22.817,63.048 22.844,63.075 22.851,63.075 22.879,63.102 22.877,63.104 22.95,63.177 22.95,63.186 24.76,64.995 25.358,64.995 ccw(c25.358,65.455) 25.817,65.455 25.817,65.646 cw(c25.947,65.646) 25.947,65.776 26.012,65.776 cw(c26.012,65.646) 26.142,65.646 26.142,63.855 ccw(c26.602,63.855) 26.602,63.395 26.667,63.395 ccw(c26.667,63.855) 27.127,63.855 27.127,66.466 cw(c27.256,66.466) 27.256,66.595 27.322,66.595 cw(c27.322,66.466) 27.451,66.466 27.451,65.455 ccw(c27.911,65.455) 27.911,64.995 41.58,64.995 46.15,60.425 46.15,59.25 46.975,58.425 46.975,52.282 47.507,51.75 47.747,51.75 47.82,51.677 v1(47.82,51.28)
MIPI_DSI0_DATA0_N: L24.1 U1.AN9 | length 49.3
  Top w0.102: L24.1@31.35,61.975 31.35,61.549 31.256,61.455 31.258,61.454 31.258,61.307 31.54,61.025 31.543,61.028 v1(31.677,61.028) ; v1(47.82,48.74) 47.82,48.73 U1.AN9@48.43,48.12
  Signal_3 w0.124: v1(31.677,61.028) 31.677,60.973 31.652,60.948 31.698,60.902 32,60.902 32.174,61.076 32.234,61.136 ccw(c32.144,61.226) 32.234,61.316 32.093,61.457 cw(c32.183,61.547) 32.093,61.637 32.213,61.757 cw(c32.303,61.667) 32.393,61.757 32.534,61.616 ccw(c32.624,61.706) 32.714,61.616 32.975,61.877 32.975,62.15 32.925,62.2 31.542,62.2 31.033,61.692 30.937,61.595 29.049,61.595 28.952,61.692 28.095,62.549 28.095,63.72 28.908,64.533 29.005,64.63 36.571,64.63 cw(c36.571,64.23) 36.972,64.23 ccw(c37.102,64.23) 37.102,64.1 37.167,64.1 ccw(c37.167,64.23) 37.297,64.23 cw(c37.697,64.23) 37.697,64.63 37.822,64.63 cw(c37.822,64.171) 38.281,64.171 38.281,63.76 ccw(c38.411,63.76) 38.411,63.63 38.476,63.63 ccw(c38.476,63.76) 38.606,63.76 38.606,64.171 cw(c39.066,64.171) 39.066,64.63 41.388,64.63 43.605,62.413 43.605,61.439 43.266,61.1 42.817,61.1 42.525,60.808 42.525,60.25 42.725,60.05 44.625,60.05 46.65,58.025 46.65,52.017 47.23,51.437 47.23,48.606 47.566,48.27 47.747,48.27 47.82,48.343 v1(47.82,48.74)
MIPI_DSI0_DATA0_P: L24.4 U1.AN10 | length 49.3
  Top w0.102: L24.4@30.8,61.975 30.8,61.549 30.954,61.395 30.954,61.069 31.575,60.448 v1(31.588,60.448) ; v1(47.82,47.47) 47.82,47.46 U1.AN10@48.43,46.85
  Signal_3 w0.124: v1(31.588,60.448) 31.588,60.461 31.698,60.571 32.137,60.571 33.208,61.643 33.305,61.74 33.305,62.287 33.208,62.383 33.062,62.53 31.405,62.53 31.275,62.4 30.75,61.875 29.235,61.875 28.425,62.685 28.425,63.583 29.142,64.3 36.571,64.3 cw(c36.571,64.23) 36.642,64.23 ccw(c37.102,64.23) 37.102,63.77 37.167,63.77 ccw(c37.167,64.23) 37.627,64.23 cw(c37.697,64.23) 37.697,64.3 37.822,64.3 cw(c37.822,64.171) 37.951,64.171 37.951,63.76 ccw(c38.411,63.76) 38.411,63.3 38.476,63.3 ccw(c38.476,63.76) 38.936,63.76 38.936,64.171 cw(c39.066,64.171) 39.066,64.3 41.251,64.3 43.275,62.276 43.275,61.576 43.099,61.4 42.65,61.4 42.195,60.945 42.195,60.075 42.57,59.7 44.495,59.7 46.35,57.845 46.35,51.85 46.9,51.3 46.9,48.469 47.43,47.94 47.747,47.94 47.82,47.867 v1(47.82,47.47)
MIPI_DSI0_DATA1_N: L25.1 U1.AN12 | length 54.8
  Top w0.102: v1(47.82,44.93) 47.82,44.92 U1.AN12@48.43,44.31
  Top w0.124: L25.1@27.6,61.975 27.6,61.75 27.675,61.675 28.2,61.675 v1(28.25,61.625)
  Signal_3 w0.124: v1(28.25,61.625) 28.25,60.95 28.06,60.76 26.385,60.76 26.2,60.575 26.2,60.075 26.392,59.883 31.596,59.883 31.747,60.034 31.76,60.034 31.771,60.044 33.344,60.044 33.43,60.13 33.43,61.172 34.283,62.025 35.312,62.025 cw(c35.312,61.565) 35.772,61.565 35.772,60.554 ccw(c35.902,60.554) 35.902,60.425 35.967,60.425 ccw(c35.967,60.554) 36.097,60.554 36.097,62.114 cw(c36.556,62.114) 36.556,62.574 36.622,62.574 cw(c36.622,62.114) 37.081,62.114 ccw(c37.17,62.114) 37.17,62.025 37.317,62.025 ccw(c37.317,62.114) 37.406,62.114 cw(c37.866,62.114) 37.866,62.574 37.931,62.574 cw(c37.931,62.114) 38.391,62.114 ccw(c38.48,62.114) 38.48,62.025 38.991,62.025 39.058,61.958 40.409,61.958 41.249,61.118 41.249,60.584 cw(c41.189,60.128) 41.649,60.128 41.649,60.063 cw(c41.189,60.063) 41.249,59.607 41.249,58.909 38.9,56.561 38.9,53.775 40.023,52.652 44.438,52.652 44.57,52.784 44.57,53.661 44.617,53.661 45.012,54.055 45.412,54.055 45.73,53.737 45.73,52.041 46.463,51.308 46.463,48.187 47.212,47.438 47.212,46.1 47.212,46.015 ccw(c47.339,46.015) 47.339,45.888 47.449,45.888 cw(c47.449,45.76) 47.577,45.76 47.577,45.591 cw(c47.449,45.591) 47.449,45.463 47.339,45.463 ccw(c47.339,45.336) 47.212,45.336 47.212,45.25 47.212,44.892 47.644,44.46 47.747,44.46 47.82,44.533 v1(47.82,44.93)
MIPI_DSI0_DATA1_P: L25.4 U1.AN13 | length 54.8
  Top w0.102: v1(47.82,43.66) 47.82,43.65 U1.AN13@48.43,43.04
  Top w0.124: L25.4@27.05,61.975 27.05,61.5 27.201,61.349 27.651,61.349 v1(27.825,61.175)
  Signal_3 w0.124: v1(27.825,61.175) 27.74,61.09 27.46,61.09 27.35,61.2 27.16,61.2 27.05,61.09 26.248,61.09 26.089,60.931 25.967,60.808 25.87,60.712 25.87,59.938 25.967,59.842 26.255,59.553 31.732,59.553 31.894,59.714 33.481,59.714 33.76,59.993 33.76,61.035 34.42,61.695 35.312,61.695 cw(c35.312,61.565) 35.442,61.565 35.442,60.554 ccw(c35.902,60.554) 35.902,60.095 35.967,60.095 ccw(c35.967,60.554) 36.427,60.554 36.427,62.114 cw(c36.556,62.114) 36.556,62.243 36.622,62.243 cw(c36.622,62.114) 36.751,62.114 ccw(c37.17,62.114) 37.17,61.695 37.317,61.695 ccw(c37.317,62.114) 37.736,62.114 cw(c37.866,62.114) 37.866,62.243 37.931,62.243 cw(c37.931,62.114) 38.061,62.114 ccw(c38.48,62.114) 38.48,61.695 38.854,61.695 38.921,61.628 40.272,61.628 40.918,60.982 40.918,60.528 ccw(c41.189,60.528) 41.189,60.258 cw(c41.189,60.128) 41.318,60.128 41.318,60.063 cw(c41.189,60.063) 41.189,59.933 ccw(c41.189,59.663) 40.918,59.663 40.918,58.999 38.574,56.654 38.574,53.651 39.903,52.322 44.575,52.322 44.9,52.647 44.9,53.575 45.05,53.725 45.275,53.725 45.4,53.6 45.4,51.904 46.133,51.171 46.133,48.05 46.882,47.301 46.882,44.755 47.507,44.13 47.747,44.13 47.82,44.057 v1(47.82,43.66)
MIPI_DSI0_DATA2_N: L26.1 U1.AN15 | length 48
  Top w0.102: v1(46.6,40.1) 48.03,40.1 U1.AN15@48.43,40.5
  Top w0.124: L26.1@23.85,61.975 23.75,61.875 23.75,61.425 v1(24.05,61.125)
  Signal_3 w0.124: v1(24.05,61.125) 24.05,61.078 24.728,60.4 24.788,60.34 ccw(c24.878,60.43) 24.968,60.34 25.091,60.463 cw(c25.181,60.373) 25.271,60.463 25.391,60.343 cw(c25.301,60.253) 25.391,60.163 25.268,60.04 ccw(c25.358,59.95) 25.268,59.86 25.326,59.801 26.298,58.83 26.751,58.83 ; 26.762,58.841 cw(c27.222,58.841) 27.222,59.301 27.287,59.301 cw(c27.287,58.841) 27.747,58.841 27.747,58.653 ccw(c27.877,58.653) 27.877,58.523 27.942,58.523 ccw(c27.942,58.653) 28.072,58.653 28.072,58.841 cw(c28.531,58.841) 28.531,59.301 28.597,59.301 cw(c28.597,58.841) 29.056,58.841 29.056,58.665 ccw(c29.167,58.665) 29.167,58.554 29.27,58.554 ccw(c29.27,58.665) 29.381,58.665 29.381,58.841 cw(c29.841,58.841) 29.841,59.301 29.906,59.301 cw(c29.906,58.841) 30.366,58.841 30.366,58.665 ccw(c30.461,58.665) 30.461,58.57 30.595,58.57 ccw(c30.595,58.665) 30.69,58.665 30.69,58.841 cw(c31.15,58.841) 31.15,59.301 31.215,59.301 cw(c31.215,58.841) 31.675,58.841 31.675,58.269 ccw(c31.805,58.269) 31.805,58.139 31.87,58.139 ccw(c31.87,58.269) 32,58.269 32,58.371 cw(c32.459,58.371) 32.459,58.83 33.179,58.83 ccw(c33.179,58.96) 33.309,58.96 33.309,59.003 cw(c33.769,59.003) 33.769,59.463 33.834,59.463 cw(c33.834,59.003) 34.294,59.003 34.294,58.96 ccw(c34.423,58.96) 34.423,58.83 35.745,58.83 36.85,57.725 36.85,55.675 37.575,54.95 37.575,52.15 38.574,51.151 40.074,51.151 41.249,49.976 43.591,49.976 46.55,47.017 46.55,43.025 45.975,42.45 45.975,40.317 46.262,40.03 46.53,40.03 v1(46.6,40.1)
MIPI_DSI0_DATA2_P: L26.4 U1.AN16 | length 47.9
  Top w0.102: v1(46.6,39.5) 48.16,39.5 U1.AN16@48.43,39.23
  Top w0.124: L26.4@23.3,61.975 23.3,61.75 23.45,61.6 v1(23.45,61.125)
  Signal_3 w0.124: v1(23.45,61.125) 23.864,60.711 23.95,60.711 26.161,58.5 26.751,58.5 ccw(c26.751,58.841) 27.092,58.841 cw(c27.222,58.841) 27.222,58.971 27.287,58.971 cw(c27.287,58.841) 27.417,58.841 27.417,58.653 ccw(c27.877,58.653) 27.877,58.193 27.942,58.193 ccw(c27.942,58.653) 28.402,58.653 28.402,58.841 cw(c28.531,58.841) 28.531,58.971 28.597,58.971 cw(c28.597,58.841) 28.726,58.841 28.726,58.665 ccw(c29.167,58.665) 29.167,58.224 29.27,58.224 ccw(c29.27,58.665) 29.711,58.665 29.711,58.841 cw(c29.841,58.841) 29.841,58.971 29.906,58.971 cw(c29.906,58.841) 30.036,58.841 30.036,58.665 ccw(c30.461,58.665) 30.461,58.24 30.595,58.24 ccw(c30.595,58.665) 31.02,58.665 31.02,58.841 cw(c31.15,58.841) 31.15,58.971 31.215,58.971 cw(c31.215,58.841) 31.345,58.841 31.345,58.269 ccw(c31.805,58.269) 31.805,57.809 31.87,57.809 ccw(c31.87,58.269) 32.33,58.269 32.33,58.371 cw(c32.459,58.371) 32.459,58.5 33.179,58.5 ccw(c33.179,58.96) 33.639,58.96 33.639,59.003 cw(c33.769,59.003) 33.769,59.133 33.834,59.133 cw(c33.834,59.003) 33.963,59.003 33.963,58.96 ccw(c34.423,58.96) 34.423,58.5 35.622,58.5 36.524,57.599 36.524,55.546 37.25,54.819 37.25,52.025 38.425,50.85 39.925,50.85 41.1,49.675 43.425,49.675 46.22,46.88 46.22,43.162 45.675,42.617 45.675,40.15 46.125,39.7 46.4,39.7 v1(46.6,39.5)
MIPI_DSI0_DATA3_N: L28.1 U1.AN18 | length 51.8
  Top w0.102: L28.1@18.45,63.375 19.1,63.375 v1(19.25,63.225) ; v1@47.72,36.38 v1@47.773,36.327 ; v1(47.777,36.327) v1@47.773,36.327 ; U1.AN18@48.43,36.69 48.43,36.369 48.281,36.22 47.88,36.22 47.775,36.325 v1@47.773,36.327
  Signal_3 w0.124: v1(19.25,63.225) 19.338,63.225 19.485,63.078 19.797,63.078 20.074,62.801 20.074,62.377 ; 20.075,62.376 20.075,59.742 23.792,56.025 30.683,56.025 31.258,56.6 34.1,56.6 34.841,55.859 35.558,55.859 36.875,54.542 36.875,51.8 38.475,50.2 38.475,48.875 40.35,47 45.4,47 45.83,46.57 45.83,43.325 45.354,42.849 45.354,39.413 46.83,37.937 46.83,37.17 47,37 47.325,37 47.425,36.9 47.425,36.575 47.673,36.327 v1(47.777,36.327)
MIPI_DSI0_DATA3_P: L28.4 U1.AN19 | length 51.8
  Top w0.102: L28.4@18.45,62.825 19,62.825 19.225,62.6 v1(19.313,62.6) ; v1(47.248,36.04) 47.248,36.036 47.394,35.89 48.281,35.89 48.43,35.741 U1.AN19@48.43,35.42
  Signal_3 w0.124: v1(19.313,62.6) 19.46,62.747 19.661,62.747 19.744,62.664 19.744,62.24 ; 19.745,62.239 19.745,59.605 23.675,55.675 30.8,55.675 31.395,56.27 33.963,56.27 34.704,55.529 35.421,55.529 36.6,54.35 36.6,51.65 38.175,50.075 38.175,48.8 40.292,46.683 45.25,46.683 45.5,46.433 45.5,43.462 45.024,42.986 45.024,39.276 45.1,39.2 46.5,37.8 46.5,37.033 47.067,36.467 47.067,36.448 47.292,36.222 47.248,36.178 v1(47.248,36.04)
MIPI_DSI0_I2C0_SCL: J14.17 R180.1 U1.V1 | length 79
  Top w0.127: v1(13.013,63.76) 13.02,63.76 13.25,63.99 J14.17@13.25,65.1 ; v1(67.075,59) 67.075,58.685 U1.V1@67.48,58.28
  Signal_4 w0.142: v1(9.2,61.775) 8.225,61.775 7.775,61.325 7.775,59.425 8.056,59.144 10.231,59.144 11.125,58.25 12.859,58.25 13.909,57.2 21.86,57.2 22.427,56.633 26.86,56.633 27.333,57.106 33.407,57.106 37.344,61.043 37.344,61.493 37.727,61.875 42.273,61.875 42.827,62.429 52.092,62.429 52.833,61.688 52.833,61.684 54.123,60.394 55.562,60.394 55.806,60.15 59.919,60.15 60.302,59.767 63.387,59.767 64.154,59 v1(67.075,59)
  Bottom w0.127: v1(9.2,61.775) 8.459,62.516 8.459,63.522 10.062,65.125 13.02,65.125 13.013,65.118 v1(13.013,63.76)
MIPI_DSI0_I2C0_SDA: J14.18 R179.1 U1.W1 | length 72.3
  Top w0.127: J14.18@12,65.1 12,64.05 12.15,63.9 v1(12.15,63.625) ; U1.W1@66.21,58.28 65.25,59.24 65.25,63.55 65.782,64.082 66.146,64.082 67.1,65.037 v1(67.1,65.225)
  Signal_4 w0.142: v1(12.15,63.625) 12.15,63.252 13.378,62.023 17.443,62.023 19.897,64.478 26.378,64.478 26.4,64.5 30.805,64.5 31.225,64.92 35.162,64.92 36.675,66.434 37.959,66.434 38.175,66.65 41.675,66.65 42.4,67.375 49.891,67.375 50.616,66.65 52.377,66.65 53.03,67.303 60.598,67.303 62.051,65.851 62.699,65.851 64.65,63.9 66.5,63.9 67.1,64.5 v1(67.1,65.225)
  Bottom w0.127: R179.1@11.3,64.53 11.67,64.53 12.15,64.05 v1(12.15,63.625)
MIPI_DSI0_IRQ_N: R251.2 R252.1 U1.AG14 U22.1 | length 63.1
  Top w0.127: R252.1@19.4,60.195 R251.2@19.4,59.28 ; U22.1@20.525,58.995 20.24,59.28 R251.2@19.4,59.28 ; v1(20.707,51.488) 20.488,51.488 20.375,51.375 19.875,51.875 18.95,51.875 18.534,52.291 18.534,54.077 19.467,55.01 19.467,55.293 19.667,55.493 19.667,57.133 19.016,57.784 19.016,57.84 18.725,58.131 18.725,58.605 R251.2@19.4,59.28 ; v1(55.44,42.39) 55.44,42.38 U1.AG14@56.05,41.77
  Signal_4 w0.142: v1(20.707,51.488) 20.82,51.375 21.425,51.375 21.442,51.375 ccw(c21.442,51.529) 21.596,51.529 21.596,51.957 cw(c21.75,51.957) 21.75,52.111 21.784,52.111 cw(c21.784,51.957) 21.938,51.957 21.938,51.375 21.938,51.001 ccw(c22.092,51.001) 22.092,50.847 22.127,50.847 ccw(c22.127,51.001) 22.281,51.001 22.281,51.375 cw(c22.435,51.375) 22.435,51.529 22.469,51.529 cw(c22.469,51.375) 22.623,51.375 22.623,50.793 ccw(c22.777,50.793) 22.777,50.639 22.811,50.639 ccw(c22.811,50.793) 22.965,50.793 22.965,51.221 cw(c23.119,51.221) 23.119,51.375 23.425,51.375 23.675,51.375 24.225,50.825 27.9,50.825 29.503,52.428 30.172,52.428 30.9,51.7 34.15,51.7 34.85,52.4 37.05,52.4 37.252,52.198 43.647,52.198 43.704,52.141 44.081,52.141 44.675,51.547 45.025,51.547 45.273,51.795 45.273,52.223 45.45,52.4 48.339,49.511 48.339,48.636 49,47.975 55.533,47.975 55.975,47.533 55.975,42.925 v1(55.44,42.39)
MIPI_DSI0_PWM0_OUT: J14.16 U1.Y1 | length 76.6
  Top w0.127: v1(12.943,63.182) 13.262,63.182 14.5,64.42 J14.16@14.5,65.1 ; U1.Y1@64.94,58.28 64.94,63.599 65.677,64.336 66.041,64.336 66.684,64.98 66.684,65.76 66.925,66 v1(66.925,66.025)
  Signal_4 w0.142: v1(12.943,63.182) 13.832,62.293 17.152,62.293 19.629,64.769 21.45,64.769 21.467,64.769 ccw(c21.467,64.923) 21.621,64.923 21.621,65.302 cw(c21.775,65.302) 21.775,65.456 21.809,65.456 cw(c21.809,65.302) 21.963,65.302 21.963,64.923 ccw(c22.117,64.923) 22.117,64.769 22.152,64.769 ccw(c22.152,64.923) 22.306,64.923 22.306,65.293 cw(c22.46,65.293) 22.46,65.447 22.494,65.447 cw(c22.494,65.293) 22.648,65.293 22.648,64.923 ccw(c22.802,64.923) 22.802,64.769 22.836,64.769 ccw(c22.836,64.923) 22.99,64.923 22.99,65.293 cw(c23.144,65.293) 23.144,65.447 23.178,65.447 cw(c23.178,65.293) 23.332,65.293 23.332,64.923 ccw(c23.486,64.923) 23.486,64.769 23.521,64.769 ccw(c23.521,64.923) 23.675,64.923 23.675,65.293 cw(c23.829,65.293) 23.829,65.447 23.863,65.447 cw(c23.863,65.293) 24.017,65.293 24.017,64.923 ccw(c24.171,64.923) 24.171,64.769 24.205,64.769 ccw(c24.205,64.923) 24.359,64.923 24.359,65.293 cw(c24.513,65.293) 24.513,65.447 24.547,65.447 cw(c24.547,65.293) 24.701,65.293 24.701,64.923 ccw(c24.855,64.923) 24.855,64.769 24.89,64.769 ccw(c24.89,64.923) 25.044,64.923 25.044,65.293 cw(c25.198,65.293) 25.198,65.447 25.232,65.447 cw(c25.232,65.293) 25.386,65.293 25.386,64.923 ccw(c25.54,64.923) 25.54,64.769 25.574,64.769 ccw(c25.574,64.923) 25.728,64.923 25.728,65.293 cw(c25.882,65.293) 25.882,65.447 25.916,65.447 cw(c25.916,65.293) 26.07,65.293 26.07,64.874 ccw(c26.175,64.874) 26.175,64.769 30.693,64.769 31.114,65.189 35.05,65.189 37.536,67.675 47.16,67.675 47.275,67.79 52.113,67.79 52.26,67.642 64.283,67.642 65.4,66.525 66.425,66.525 v1(66.925,66.025)
MIPI_DSI1_CLK_N: L34.1 U1.AJ19 | length 33.5
  Top w0.102: L34.1@51.275,62.15 51.165,62.04 51.165,61.506 51.354,61.317 51.533,61.317 51.603,61.247 v1(51.603,61.178) ; U1.AJ19@53.51,35.42 54.095,34.835 54.1,34.83 v1(54.1,34.84)
  Signal_3 w0.124: v1(51.603,61.178) 51.603,61.247 51.538,61.312 51.359,61.312 51.058,61.613 50.682,61.613 50.381,61.311 50.381,58.057 50.79,57.647 50.79,55.463 51.196,55.057 51.196,53.496 51.728,52.964 51.802,52.964 52.044,52.722 52.044,52.648 52.05,52.642 52.05,43.59 52.039,43.579 52.039,43.553 51.797,43.311 51.771,43.311 51.607,43.147 51.3,43.147 50.846,42.693 50.846,38.637 51.716,37.766 51.724,37.766 51.967,37.523 51.967,37.516 52.034,37.448 52.034,36.021 52.414,35.641 52.702,35.641 52.731,35.613 53.074,35.613 53.103,35.641 53.304,35.641 54.103,34.842 54.105,34.84 v1(54.1,34.84)
MIPI_DSI1_CLK_P: L34.4 U1.AJ18 | length 33.3
  Top w0.102: L34.4@50.725,62.15 50.835,62.04 50.835,61.369 51.058,61.146 51.058,60.967 51.24,60.785 51.227,60.773 v1(51.227,60.728) ; v1(52.903,36.027) 52.903,36.043 52.92,36.06 53.32,36.06 53.51,36.25 U1.AJ18@53.51,36.69
  Signal_3 w0.124: v1(51.227,60.728) 51.227,60.773 51.24,60.785 51.063,60.962 51.063,61.141 50.922,61.282 50.818,61.282 50.711,61.175 50.711,60.32 50.711,60.304 ccw(c50.857,60.304) 50.857,60.158 51.29,60.158 cw(c51.29,60.012) 51.436,60.012 51.436,59.979 cw(c51.29,59.979) 51.29,59.833 50.857,59.833 ccw(c50.857,59.687) 50.711,59.687 50.711,59.655 ccw(c50.857,59.655) 50.857,59.509 51.109,59.509 cw(c51.109,59.363) 51.255,59.363 51.255,59.33 cw(c51.109,59.33) 51.109,59.184 50.857,59.184 ccw(c50.857,59.038) 50.711,59.038 50.711,58.96 50.711,58.193 51.12,57.784 51.12,55.6 51.526,55.194 51.526,53.633 52.322,52.837 52.322,43.395 51.743,42.816 51.436,42.816 51.176,42.556 51.176,38.773 52.364,37.585 52.364,36.158 52.551,35.971 52.693,35.971 52.802,36.08 52.855,36.027 v1(52.903,36.027)
MIPI_DSI1_DATA0_N: L31.1 U1.AJ15 | length 33.6
  Top w0.102: U1.AJ15@53.51,40.5 54.12,41.11 v1(54.13,41.11) ; L31.1@62.475,62.15 62.475,61.724 62.365,61.614 62.365,61.273 62.52,61.119 v1(62.52,61.08)
  Signal_3 w0.124: v1(54.13,41.11) 54.13,40.713 54.203,40.64 54.443,40.64 54.965,40.118 54.965,39.749 55.253,39.461 57.111,39.461 57.375,39.725 57.375,56.191 57.375,57.892 58.103,58.62 59.745,58.62 60.442,59.317 60.442,60.301 60.435,60.308 60.435,60.411 60.433,60.411 60.433,60.449 60.438,60.455 60.438,60.492 60.441,60.496 60.441,60.533 ; 60.442,60.533 60.442,60.968 ; 60.441,60.968 60.441,61.005 60.438,61.009 60.438,61.046 60.433,61.052 60.433,61.09 60.435,61.09 60.435,61.193 60.442,61.2 60.442,61.608 60.849,62.016 62.099,62.016 62.365,61.749 62.365,61.361 62.52,61.207 v1(62.52,61.08)
MIPI_DSI1_DATA0_P: L31.4 U1.AJ16 | length 33.6
  Top w0.102: U1.AJ16@53.51,39.23 54.12,39.84 v1(54.13,39.84) ; v1(61.9,61.08) 61.9,61.139 62.035,61.273 62.035,61.614 61.925,61.724 L31.4@61.925,62.15
  Signal_3 w0.124: v1(54.13,39.84) 54.13,40.237 54.203,40.31 54.306,40.31 54.635,39.981 54.635,39.613 55.117,39.131 57.248,39.131 57.705,39.588 57.705,56.327 57.705,57.755 58.24,58.29 59.89,58.29 60.772,59.172 60.772,60.275 60.772,60.411 cw(c60.899,60.411) 60.899,60.538 61.027,60.538 ccw(c61.027,60.666) 61.155,60.666 61.155,60.835 ccw(c61.027,60.835) 61.027,60.963 60.899,60.963 cw(c60.899,61.09) 60.772,61.09 60.772,61.175 60.772,61.472 60.985,61.685 61.962,61.685 62.035,61.612 62.035,61.361 61.9,61.227 v1(61.9,61.08)
MIPI_DSI1_DATA1_N: L32.1 U1.AK15 | length 32.8
  Top w0.102: U1.AK15@52.24,40.5 52.85,41.11 v1(52.86,41.11) ; L32.1@58.775,62.15 58.775,61.724 58.665,61.614 58.665,61.273 58.7,61.238 v1(58.789,61.238)
  Signal_3 w0.124: v1(52.86,41.11) 52.86,40.713 52.933,40.64 53.036,40.64 53.358,40.962 53.358,41.391 53.913,41.946 54.21,41.946 54.292,42.028 54.32,42.028 54.532,42.24 54.532,42.268 54.625,42.361 54.625,52.735 53.32,54.04 53.32,56.695 53.428,56.803 53.428,56.871 ccw(c53.25,56.871) 53.25,57.048 cw(c53.25,57.508) 52.791,57.508 52.791,57.573 cw(c53.25,57.573) 53.25,58.033 53.932,58.033 ccw(c53.932,58.163) 54.062,58.163 54.062,58.228 ccw(c53.932,58.228) 53.932,58.358 53.887,58.358 cw(c53.887,58.817) 53.428,58.817 53.428,61.395 54.13,62.097 58.381,62.097 58.647,61.831 58.647,61.468 58.789,61.326 v1(58.789,61.238)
